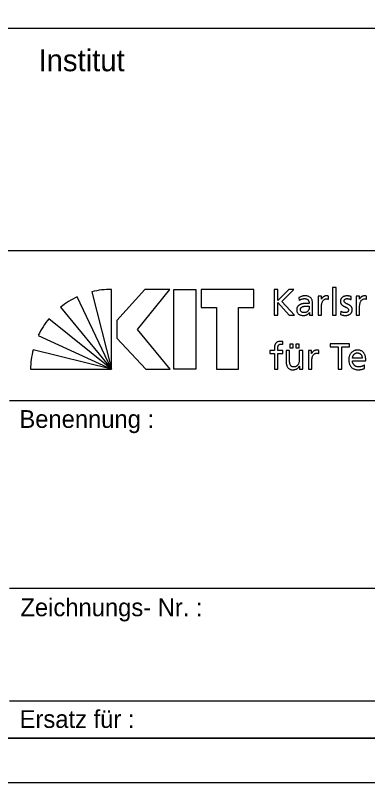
# Model space of a CAD drawing. Extents: x 0 to 210, y 0 to 148.
# Drawn here: x 188.16 to 198.08, y 0 to 21.62 of the extents above; entities that cross this region are included whole.
import ezdxf

# ---------------------------------------------------------------- set-up
doc = ezdxf.new("R2010")
doc.units = 0
doc.layers.add('90_Plankopf', color=7, linetype='Continuous')

msp = doc.modelspace()

# ---------------------------------------------------------------- linework, layer by layer
at = {"layer": '90_Plankopf'}
for p, q in [((209, 21.248), (164.53, 21.248)), ((164.53, 14.998), (209, 14.998)), ((164.53, 14.998), (209, 14.998)), ((190.87, 11.647), (190.87, 13.896)), ((195.452, 13.897), (195.452, 13.176)), ((190.87, 11.647), (189.908, 13.688)), ((190.319, 13.833), (190.87, 11.647)), ((196.145, 13.665), (196.15, 13.583)), ((196.982, 13.621), (196.982, 13.708)), ((197.614, 13.61), (197.622, 13.694)), ((198.053, 13.621), (198.053, 13.708)), ((196.433, 13.427), (196.433, 13.381)), ((196.53, 13.28), (196.53, 13.497)), ((189.436, 13.396), (190.87, 11.647)), ((197.324, 13.28), (197.319, 13.193)), ((190.87, 11.647), (189.108, 13.071)), ((195.452, 13.176), (195.556, 13.176)), ((195.876, 13.176), (196.027, 13.176)), ((188.81, 12.603), (190.87, 11.647)), ((195.693, 12.348), (195.697, 12.427)), ((190.87, 11.647), (188.664, 12.197)), ((196.707, 12.091), (196.707, 12.178)), ((197.927, 11.96), (197.654, 11.96)), ((197.654, 11.888), (198.03, 11.888)), ((197.989, 11.668), (197.989, 11.765)), ((188.591, 11.647), (190.87, 11.647)), ((188, 10.768), (209, 10.768)), ((188, 5.48), (209, 5.48)), ((188, 2.308), (209, 2.308)), ((209, 1.25), (164.53, 1.25)), ((167.45, 1.25), (209, 1.25)), ((167.45, 1.25), (209, 1.25))]:
    msp.add_line(p, q, dxfattribs=at)
for points in [[(0, 0), (210.25, 0), (210.25, 148.5), (0, 148.5)], [(6.25, 147.25), (209, 147.25), (209, 1.25), (6.25, 1.25)], [(192.517, 13.897), (191.809, 13.897), (191.018, 13.025), (191.018, 12.523), (191.834, 11.647), (192.521, 11.647), (191.606, 12.766)], [(193.243, 13.897), (193.243, 11.647), (192.625, 11.647), (192.625, 13.897)], [(193.391, 13.897), (193.391, 13.39), (193.825, 13.39), (193.825, 11.647), (194.443, 11.647), (194.443, 13.39), (194.877, 13.39), (194.877, 13.897)]]:
    msp.add_lwpolyline(points, close=True, dxfattribs=at)
for points in [[(196.027, 13.176), (195.662, 13.556), (196, 13.897), (195.863, 13.897), (195.556, 13.58), (195.556, 13.897), (195.452, 13.897)], [(197.095, 13.176), (197.192, 13.176), (197.192, 13.95), (197.095, 13.95), (197.095, 13.176)], [(196.78, 13.621), (196.778, 13.621), (196.778, 13.703), (196.688, 13.703), (196.688, 13.176), (196.785, 13.176), (196.785, 13.416)], [(197.852, 13.621), (197.85, 13.621), (197.85, 13.703), (197.759, 13.703), (197.759, 13.176), (197.856, 13.176), (197.856, 13.416)], [(195.556, 13.176), (195.556, 13.529), (195.876, 13.176)], [(196.441, 13.245), (196.443, 13.245), (196.443, 13.176), (196.534, 13.176)], [(195.889, 12.356), (195.889, 12.253), (195.986, 12.253), (195.986, 12.356), (195.889, 12.356)], [(196.058, 12.356), (196.058, 12.253), (196.155, 12.253), (196.155, 12.356), (196.058, 12.356)], [(197.248, 11.647), (197.351, 11.647), (197.351, 12.276), (197.575, 12.276), (197.575, 12.367), (197.024, 12.367), (197.024, 12.276), (197.248, 12.276), (197.248, 11.647)], [(195.456, 12.221), (195.456, 12.173), (195.332, 12.173), (195.332, 12.094), (195.456, 12.094), (195.456, 11.647), (195.553, 11.647), (195.553, 12.094), (195.692, 12.094), (195.692, 12.173), (195.553, 12.173), (195.553, 12.23)], [(195.885, 11.9), (195.885, 12.173), (195.788, 12.173), (195.788, 11.86)], [(196.254, 11.647), (196.254, 12.173), (196.157, 12.173), (196.157, 11.929)], [(196.506, 12.091), (196.504, 12.091), (196.504, 12.173), (196.413, 12.173), (196.413, 11.647), (196.51, 11.647), (196.51, 11.886)], [(196.158, 11.73), (196.16, 11.73), (196.16, 11.647), (196.254, 11.647)]]:
    msp.add_lwpolyline(points, dxfattribs=at)
for centre, start, end in [((190.862, 11.514), 89.8053, 103.1895), ((190.915, 11.529), 115.0126, 128.3968), ((190.954, 11.566), 140.7898, 154.174), ((190.973, 11.609), 165.7222, 179.1064)]:
    msp.add_arc(centre, 2.382, start, end, dxfattribs=at)
for points in [[(196.53, 13.497), (196.53, 13.545), (196.523, 13.585), (196.508, 13.617), (196.494, 13.65), (196.471, 13.674), (196.44, 13.69), (196.409, 13.707), (196.368, 13.715), (196.318, 13.715), (196.285, 13.715), (196.253, 13.71), (196.224, 13.701), (196.195, 13.692), (196.169, 13.68), (196.145, 13.665)], [(196.15, 13.583), (196.163, 13.594), (196.178, 13.604), (196.195, 13.611), (196.211, 13.62), (196.229, 13.626), (196.247, 13.63), (196.266, 13.634), (196.284, 13.637), (196.303, 13.637), (196.335, 13.637), (196.36, 13.631), (196.379, 13.621), (196.399, 13.611), (196.412, 13.596), (196.42, 13.575), (196.429, 13.555), (196.433, 13.53), (196.433, 13.499)], [(196.982, 13.708), (196.975, 13.709), (196.968, 13.71), (196.962, 13.712), (196.956, 13.713), (196.949, 13.713), (196.942, 13.714), (196.935, 13.715), (196.927, 13.715), (196.918, 13.715), (196.899, 13.715), (196.881, 13.711), (196.863, 13.703), (196.845, 13.695), (196.829, 13.684), (196.815, 13.67), (196.801, 13.656), (196.789, 13.639), (196.78, 13.621)], [(196.785, 13.416), (196.785, 13.46), (196.791, 13.498), (196.802, 13.53), (196.814, 13.562), (196.831, 13.587), (196.852, 13.604), (196.874, 13.621), (196.899, 13.63), (196.928, 13.63), (196.936, 13.631), (196.945, 13.63), (196.954, 13.629), (196.964, 13.627), (196.973, 13.625), (196.982, 13.621)], [(197.622, 13.694), (197.604, 13.7), (197.584, 13.705), (197.565, 13.709), (197.545, 13.713), (197.524, 13.715), (197.502, 13.715), (197.476, 13.715), (197.451, 13.712), (197.429, 13.705), (197.406, 13.698), (197.387, 13.688), (197.37, 13.675), (197.353, 13.662), (197.34, 13.645), (197.33, 13.625), (197.321, 13.604), (197.316, 13.58), (197.316, 13.553), (197.316, 13.532), (197.321, 13.514), (197.329, 13.498), (197.337, 13.483), (197.348, 13.47), (197.361, 13.459), (197.375, 13.447), (197.39, 13.437), (197.406, 13.429), (197.422, 13.42), (197.438, 13.412), (197.454, 13.404), (197.471, 13.397), (197.485, 13.389), (197.499, 13.38), (197.512, 13.373), (197.523, 13.363), (197.532, 13.353), (197.54, 13.343), (197.544, 13.331), (197.544, 13.318), (197.544, 13.304), (197.541, 13.292), (197.535, 13.282), (197.529, 13.272), (197.521, 13.265), (197.511, 13.259), (197.501, 13.253), (197.491, 13.249), (197.479, 13.246), (197.468, 13.244), (197.456, 13.242), (197.445, 13.242), (197.435, 13.242), (197.424, 13.244), (197.41, 13.247), (197.396, 13.249), (197.381, 13.253), (197.366, 13.259), (197.351, 13.265), (197.337, 13.271), (197.324, 13.28)], [(197.319, 13.193), (197.342, 13.181), (197.365, 13.174), (197.389, 13.17), (197.414, 13.166), (197.439, 13.164), (197.464, 13.164), (197.487, 13.164), (197.51, 13.167), (197.532, 13.174), (197.554, 13.18), (197.573, 13.191), (197.591, 13.204), (197.608, 13.217), (197.622, 13.234), (197.632, 13.255), (197.642, 13.276), (197.647, 13.3), (197.647, 13.328), (197.647, 13.352), (197.643, 13.372), (197.635, 13.389), (197.626, 13.406), (197.616, 13.42), (197.602, 13.431), (197.589, 13.443), (197.574, 13.453), (197.557, 13.461), (197.541, 13.469), (197.525, 13.477), (197.509, 13.484), (197.493, 13.491), (197.478, 13.499), (197.464, 13.507), (197.451, 13.515), (197.44, 13.524), (197.432, 13.534), (197.424, 13.545), (197.419, 13.557), (197.419, 13.573), (197.419, 13.587), (197.424, 13.599), (197.432, 13.609), (197.441, 13.618), (197.452, 13.625), (197.466, 13.63), (197.48, 13.634), (197.495, 13.637), (197.512, 13.637), (197.518, 13.637), (197.526, 13.636), (197.535, 13.634), (197.544, 13.633), (197.553, 13.631), (197.564, 13.628), (197.574, 13.626), (197.583, 13.623), (197.592, 13.62), (197.601, 13.616), (197.609, 13.613), (197.614, 13.61)], [(198.053, 13.708), (198.046, 13.709), (198.04, 13.71), (198.034, 13.712), (198.027, 13.713), (198.021, 13.713), (198.014, 13.714), (198.007, 13.715), (197.998, 13.715), (197.989, 13.715), (197.97, 13.715), (197.952, 13.711), (197.934, 13.703), (197.917, 13.695), (197.901, 13.684), (197.886, 13.67), (197.872, 13.656), (197.86, 13.639), (197.852, 13.621)], [(197.856, 13.416), (197.856, 13.46), (197.862, 13.498), (197.874, 13.53), (197.886, 13.562), (197.902, 13.587), (197.923, 13.604), (197.945, 13.621), (197.97, 13.63), (197.999, 13.63), (198.008, 13.631), (198.016, 13.63), (198.026, 13.629), (198.035, 13.627), (198.044, 13.625), (198.053, 13.621)], [(196.433, 13.499), (196.42, 13.5), (196.408, 13.501), (196.397, 13.501), (196.386, 13.501), (196.376, 13.501), (196.365, 13.501), (196.354, 13.501), (196.342, 13.501), (196.329, 13.501), (196.309, 13.501), (196.288, 13.5), (196.266, 13.496), (196.243, 13.492), (196.221, 13.487), (196.2, 13.478), (196.179, 13.47), (196.16, 13.46), (196.142, 13.446), (196.125, 13.433), (196.111, 13.416), (196.101, 13.397), (196.09, 13.377), (196.085, 13.354), (196.085, 13.328), (196.085, 13.29), (196.094, 13.259), (196.11, 13.235), (196.126, 13.211), (196.149, 13.193), (196.177, 13.181), (196.206, 13.17), (196.24, 13.164), (196.278, 13.164), (196.3, 13.164), (196.32, 13.167), (196.338, 13.172), (196.355, 13.177), (196.371, 13.184), (196.384, 13.192), (196.398, 13.2), (196.409, 13.209), (196.418, 13.218), (196.428, 13.228), (196.435, 13.236), (196.441, 13.245)], [(196.433, 13.381), (196.433, 13.354), (196.427, 13.331), (196.416, 13.31), (196.405, 13.289), (196.388, 13.273), (196.367, 13.261), (196.345, 13.249), (196.318, 13.243), (196.286, 13.242), (196.275, 13.242), (196.264, 13.244), (196.252, 13.248), (196.241, 13.252), (196.23, 13.257), (196.22, 13.264), (196.211, 13.272), (196.203, 13.281), (196.197, 13.291), (196.191, 13.302), (196.188, 13.314), (196.188, 13.328), (196.188, 13.347), (196.193, 13.362), (196.202, 13.374), (196.211, 13.387), (196.223, 13.396), (196.237, 13.404), (196.252, 13.411), (196.267, 13.417), (196.284, 13.42), (196.3, 13.424), (196.316, 13.426), (196.332, 13.428), (196.347, 13.429), (196.36, 13.429), (196.371, 13.429), (196.381, 13.429), (196.391, 13.429), (196.402, 13.428), (196.412, 13.428), (196.422, 13.427), (196.433, 13.427)], [(196.534, 13.176), (196.533, 13.181), (196.532, 13.188), (196.532, 13.197), (196.531, 13.205), (196.531, 13.216), (196.53, 13.23), (196.53, 13.243), (196.53, 13.26), (196.53, 13.28)], [(195.697, 12.427), (195.688, 12.428), (195.678, 12.43), (195.667, 12.431), (195.656, 12.432), (195.645, 12.433), (195.632, 12.433), (195.597, 12.433), (195.568, 12.428), (195.544, 12.418), (195.521, 12.408), (195.503, 12.394), (195.491, 12.375), (195.478, 12.356), (195.469, 12.334), (195.464, 12.308), (195.458, 12.282), (195.456, 12.253), (195.456, 12.221)], [(195.553, 12.23), (195.553, 12.247), (195.554, 12.264), (195.556, 12.279), (195.558, 12.294), (195.562, 12.307), (195.569, 12.319), (195.575, 12.33), (195.585, 12.339), (195.597, 12.345), (195.61, 12.351), (195.626, 12.354), (195.647, 12.354), (195.655, 12.354), (195.664, 12.354), (195.672, 12.353), (195.68, 12.352), (195.688, 12.35), (195.693, 12.348)], [(196.707, 12.178), (196.7, 12.179), (196.693, 12.181), (196.688, 12.182), (196.681, 12.183), (196.675, 12.184), (196.667, 12.184), (196.661, 12.185), (196.652, 12.185), (196.643, 12.185), (196.624, 12.185), (196.606, 12.181), (196.588, 12.173), (196.571, 12.165), (196.555, 12.154), (196.54, 12.14), (196.526, 12.126), (196.514, 12.11), (196.506, 12.091)], [(198.03, 11.888), (198.03, 11.931), (198.026, 11.97), (198.018, 12.006), (198.01, 12.042), (197.997, 12.073), (197.979, 12.1), (197.961, 12.127), (197.938, 12.148), (197.908, 12.162), (197.878, 12.177), (197.841, 12.185), (197.797, 12.185), (197.76, 12.185), (197.726, 12.178), (197.696, 12.166), (197.666, 12.152), (197.64, 12.134), (197.618, 12.111), (197.597, 12.087), (197.58, 12.059), (197.569, 12.026), (197.557, 11.994), (197.551, 11.958), (197.551, 11.919), (197.551, 11.876), (197.556, 11.837), (197.567, 11.802), (197.578, 11.767), (197.595, 11.737), (197.617, 11.712), (197.639, 11.687), (197.668, 11.668), (197.702, 11.655), (197.736, 11.641), (197.777, 11.634), (197.823, 11.634), (197.852, 11.634), (197.876, 11.636), (197.897, 11.64), (197.917, 11.644), (197.934, 11.648), (197.949, 11.653), (197.964, 11.659), (197.977, 11.664), (197.989, 11.668)], [(197.654, 11.96), (197.656, 11.977), (197.66, 11.995), (197.666, 12.012), (197.672, 12.029), (197.681, 12.045), (197.692, 12.059), (197.703, 12.073), (197.717, 12.085), (197.734, 12.093), (197.751, 12.102), (197.772, 12.107), (197.795, 12.107), (197.816, 12.107), (197.835, 12.103), (197.851, 12.095), (197.867, 12.088), (197.881, 12.077), (197.892, 12.064), (197.903, 12.05), (197.912, 12.035), (197.918, 12.017), (197.924, 11.999), (197.927, 11.981), (197.927, 11.96)], [(196.157, 11.929), (196.157, 11.897), (196.154, 11.868), (196.147, 11.841), (196.141, 11.815), (196.131, 11.792), (196.118, 11.773), (196.105, 11.754), (196.088, 11.739), (196.068, 11.728), (196.048, 11.718), (196.024, 11.713), (195.997, 11.713), (195.969, 11.714), (195.947, 11.722), (195.93, 11.736), (195.914, 11.75), (195.902, 11.771), (195.895, 11.798), (195.889, 11.825), (195.885, 11.859), (195.885, 11.9)], [(196.51, 11.886), (196.51, 11.93), (196.516, 11.968), (196.528, 12), (196.539, 12.032), (196.556, 12.057), (196.577, 12.074), (196.599, 12.092), (196.624, 12.1), (196.653, 12.1), (196.662, 12.101), (196.67, 12.1), (196.68, 12.099), (196.689, 12.097), (196.698, 12.095), (196.707, 12.091)], [(195.788, 11.86), (195.788, 11.813), (195.795, 11.772), (195.809, 11.739), (195.823, 11.705), (195.845, 11.679), (195.874, 11.661), (195.903, 11.644), (195.94, 11.634), (195.986, 11.634), (196.01, 11.634), (196.034, 11.638), (196.056, 11.646), (196.079, 11.653), (196.099, 11.665), (196.117, 11.679), (196.134, 11.693), (196.148, 11.71), (196.158, 11.73)], [(197.989, 11.765), (197.983, 11.76), (197.975, 11.755), (197.963, 11.749), (197.952, 11.743), (197.939, 11.737), (197.924, 11.732), (197.909, 11.726), (197.893, 11.722), (197.876, 11.718), (197.86, 11.715), (197.844, 11.713), (197.827, 11.713), (197.804, 11.713), (197.782, 11.717), (197.762, 11.725), (197.741, 11.734), (197.722, 11.746), (197.706, 11.761), (197.69, 11.777), (197.677, 11.795), (197.668, 11.817), (197.659, 11.838), (197.654, 11.862), (197.654, 11.888)]]:
    msp.add_open_spline(points, degree=3, dxfattribs=at)

# ---------------------------------------------------------------- texts
for s, height, p in [('Institut', 0.616, (188.816, 20.044)), ('Benennung :', 0.5, (188.278, 9.995)), ('Zeichnungs- Nr. :', 0.5, (188.307, 4.69)), ('Ersatz für :', 0.5, (188.285, 1.542))]:
    msp.add_text(s, height=height, dxfattribs=at).set_placement(p)

doc.saveas('drawing.dxf')
